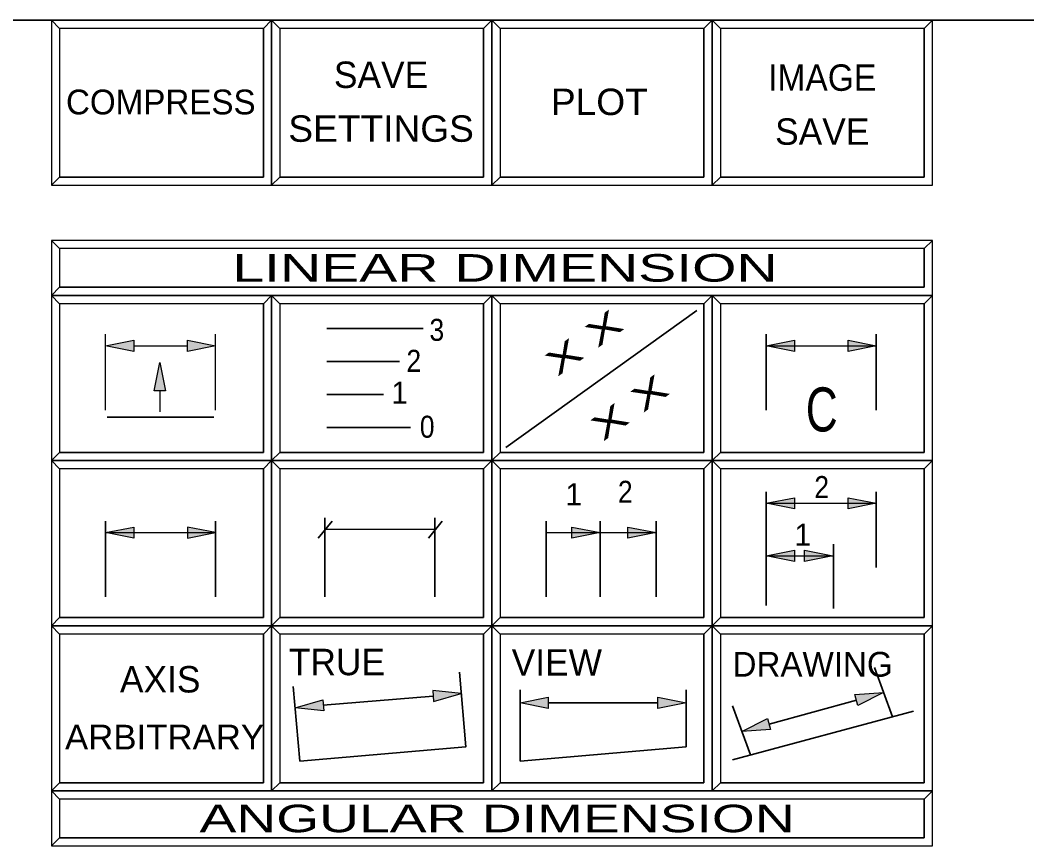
# Model space of a CAD drawing. Extents: x 95906.9 to 95918.9, y 90964.8 to 90972.9.
# Drawn here: x 95908.876 to 95910.704, y 90971.369 to 90972.862 of the extents above; entities that cross this region are included whole.
import ezdxf
from ezdxf.enums import TextEntityAlignment as Align

# ---------------------------------------------------------------- set-up
doc = ezdxf.new("R2010")
doc.units = 0
doc.header["$LTSCALE"] = 0.019
for name, color, linetype, lineweight in [('1', 7, 'Continuous', 25), ('11', 7, 'Continuous', 25), ('12', 7, 'Continuous', 25), ('17', 7, 'Continuous', 25), ('2', 7, 'Continuous', 13), ('3', 7, 'Continuous', 25), ('4', 7, 'Continuous', 35), ('6', 7, 'Continuous', 35), ('7', 7, 'Continuous', 35)]:
    doc.layers.add(name, color=color, linetype=linetype, lineweight=lineweight)

msp = doc.modelspace()

# ---------------------------------------------------------------- hatches: boundary and pattern name
at = {"layer": '6'}
for points in [[(95909.0307, 90972.2701), (95909.0819, 90972.2803), (95909.0819, 90972.2599)], [(95909.1793, 90972.2803), (95909.2305, 90972.2701), (95909.1793, 90972.2599)], [(95910.2307, 90972.2701), (95910.2819, 90972.2803), (95910.2819, 90972.2599)], [(95910.3793, 90972.2803), (95910.4305, 90972.2701), (95910.3793, 90972.2599)], [(95909.1291, 90972.2397), (95909.1393, 90972.1885), (95909.1189, 90972.1885)], [(95910.2307, 90971.9841), (95910.2819, 90971.9943), (95910.2819, 90971.9739)], [(95910.3793, 90971.9943), (95910.4305, 90971.9841), (95910.3793, 90971.9739)], [(95909.0307, 90971.9308), (95909.0819, 90971.941), (95909.0819, 90971.9206)], [(95909.2305, 90971.9308), (95909.1793, 90971.941), (95909.1793, 90971.9206)], [(95909.8778, 90971.941), (95909.929, 90971.9308), (95909.8778, 90971.9206)], [(95909.9793, 90971.941), (95910.0305, 90971.9308), (95909.9793, 90971.9206)], [(95910.2307, 90971.8889), (95910.2819, 90971.8991), (95910.2819, 90971.8787)], [(95910.3003, 90971.8991), (95910.3515, 90971.8889), (95910.3003, 90971.8787)], [(95909.6767, 90971.6384), (95909.6248, 90971.6443), (95909.6265, 90971.6239)], [(95910.3915, 90971.6366), (95910.4436, 90971.6403), (95910.397, 90971.6168)], [(95909.3751, 90971.6129), (95909.4253, 90971.6274), (95909.427, 90971.607)], [(95909.7835, 90971.6216), (95909.8347, 90971.6318), (95909.8347, 90971.6114)], [(95910.0339, 90971.6318), (95910.0851, 90971.6216), (95910.0339, 90971.6114)], [(95910.1865, 90971.5695), (95910.2331, 90971.593), (95910.2386, 90971.5732)]]:
    msp.add_hatch(color=256, dxfattribs=at).paths.add_polyline_path(points)

# ---------------------------------------------------------------- linework, layer by layer
at = {"layer": '1'}
for points in [[(95908.9323, 90972.5617), (95909.3323, 90972.5617), (95909.3323, 90972.8617), (95908.9323, 90972.8617)], [(95909.3323, 90972.5617), (95909.7323, 90972.5617), (95909.7323, 90972.8617), (95909.3323, 90972.8617)], [(95909.7323, 90972.5617), (95910.1323, 90972.5617), (95910.1323, 90972.8617), (95909.7323, 90972.8617)], [(95910.1323, 90972.5617), (95910.5323, 90972.5617), (95910.5323, 90972.8617), (95910.1323, 90972.8617)], [(95908.9323, 90972.3617), (95910.5323, 90972.3617), (95910.5323, 90972.4617), (95908.9323, 90972.4617)], [(95908.9323, 90972.0617), (95909.3323, 90972.0617), (95909.3323, 90972.3617), (95908.9323, 90972.3617)], [(95909.3323, 90972.0617), (95909.7323, 90972.0617), (95909.7323, 90972.3617), (95909.3323, 90972.3617)], [(95909.7323, 90972.0617), (95910.1323, 90972.0617), (95910.1323, 90972.3617), (95909.7323, 90972.3617)], [(95910.1323, 90972.0617), (95910.5323, 90972.0617), (95910.5323, 90972.3617), (95910.1323, 90972.3617)], [(95908.9323, 90971.7617), (95909.3323, 90971.7617), (95909.3323, 90972.0617), (95908.9323, 90972.0617)], [(95909.3323, 90971.7617), (95909.7323, 90971.7617), (95909.7323, 90972.0617), (95909.3323, 90972.0617)], [(95909.7323, 90971.7617), (95910.1323, 90971.7617), (95910.1323, 90972.0617), (95909.7323, 90972.0617)], [(95910.1323, 90971.7617), (95910.5323, 90971.7617), (95910.5323, 90972.0617), (95910.1323, 90972.0617)], [(95908.9323, 90971.4617), (95909.3323, 90971.4617), (95909.3323, 90971.7617), (95908.9323, 90971.7617)], [(95909.3323, 90971.4617), (95909.7323, 90971.4617), (95909.7323, 90971.7617), (95909.3323, 90971.7617)], [(95909.7323, 90971.4617), (95910.1323, 90971.4617), (95910.1323, 90971.7617), (95909.7323, 90971.7617)], [(95910.1323, 90971.4617), (95910.5323, 90971.4617), (95910.5323, 90971.7617), (95910.1323, 90971.7617)], [(95908.9323, 90971.3617), (95910.5323, 90971.3617), (95910.5323, 90971.4617), (95908.9323, 90971.4617)]]:
    msp.add_lwpolyline(points, close=True, dxfattribs=at)
at = {"layer": '11'}
for points in [[(95908.9473, 90972.5767), (95909.3173, 90972.5767), (95909.3173, 90972.8467), (95908.9473, 90972.8467)], [(95909.3473, 90972.5767), (95909.7173, 90972.5767), (95909.7173, 90972.8467), (95909.3473, 90972.8467)], [(95909.7473, 90972.5767), (95910.1173, 90972.5767), (95910.1173, 90972.8467), (95909.7473, 90972.8467)], [(95910.1473, 90972.5767), (95910.5173, 90972.5767), (95910.5173, 90972.8467), (95910.1473, 90972.8467)], [(95908.9473, 90972.0767), (95909.3173, 90972.0767), (95909.3173, 90972.3467), (95908.9473, 90972.3467)], [(95909.3473, 90972.0767), (95909.7173, 90972.0767), (95909.7173, 90972.3467), (95909.3473, 90972.3467)], [(95909.7473, 90972.0767), (95910.1173, 90972.0767), (95910.1173, 90972.3467), (95909.7473, 90972.3467)], [(95910.1473, 90972.0767), (95910.5173, 90972.0767), (95910.5173, 90972.3467), (95910.1473, 90972.3467)], [(95908.9473, 90971.7767), (95909.3173, 90971.7767), (95909.3173, 90972.0467), (95908.9473, 90972.0467)], [(95909.3473, 90971.7767), (95909.7173, 90971.7767), (95909.7173, 90972.0467), (95909.3473, 90972.0467)], [(95909.7473, 90971.7767), (95910.1173, 90971.7767), (95910.1173, 90972.0467), (95909.7473, 90972.0467)], [(95910.1473, 90971.7767), (95910.5173, 90971.7767), (95910.5173, 90972.0467), (95910.1473, 90972.0467)], [(95908.9473, 90971.4767), (95909.3173, 90971.4767), (95909.3173, 90971.7467), (95908.9473, 90971.7467)], [(95909.3473, 90971.4767), (95909.7173, 90971.4767), (95909.7173, 90971.7467), (95909.3473, 90971.7467)], [(95909.7473, 90971.4767), (95910.1173, 90971.4767), (95910.1173, 90971.7467), (95909.7473, 90971.7467)], [(95910.1473, 90971.4767), (95910.5173, 90971.4767), (95910.5173, 90971.7467), (95910.1473, 90971.7467)]]:
    msp.add_lwpolyline(points, close=True, dxfattribs=at)
at = {"layer": '12'}
for points in [[(95910.1473, 90972.5767), (95910.5173, 90972.5767), (95910.5173, 90972.8467), (95910.1473, 90972.8467)], [(95908.9473, 90971.7767), (95909.3173, 90971.7767), (95909.3173, 90972.0467), (95908.9473, 90972.0467)]]:
    msp.add_lwpolyline(points, close=True, dxfattribs=at)
at = {"layer": '17'}
for points in [[(95908.9473, 90972.3767), (95910.5173, 90972.3767), (95910.5173, 90972.4467), (95908.9473, 90972.4467)], [(95908.9473, 90971.3767), (95910.5173, 90971.3767), (95910.5173, 90971.4467), (95908.9473, 90971.4467)]]:
    msp.add_lwpolyline(points, close=True, dxfattribs=at)
at = {"layer": '2'}
for points in [[(95908.9323, 90972.8617), (95908.9323, 90972.5617), (95908.9473, 90972.5767), (95908.9473, 90972.8467), (95909.3173, 90972.8467), (95909.3323, 90972.8617)], [(95909.3323, 90972.8617), (95909.3323, 90972.5617), (95909.3473, 90972.5767), (95909.3473, 90972.8467), (95909.7173, 90972.8467), (95909.7323, 90972.8617)], [(95909.7323, 90972.8617), (95909.7323, 90972.5617), (95909.7473, 90972.5767), (95909.7473, 90972.8467), (95910.1173, 90972.8467), (95910.1323, 90972.8617)], [(95910.1323, 90972.8617), (95910.1323, 90972.5617), (95910.1473, 90972.5767), (95910.1473, 90972.8467), (95910.5173, 90972.8467), (95910.5323, 90972.8617)], [(95908.9323, 90972.4617), (95908.9323, 90972.3617), (95908.9473, 90972.3767), (95908.9473, 90972.4467), (95910.5173, 90972.4467), (95910.5323, 90972.4617)], [(95908.9323, 90972.3617), (95908.9323, 90972.0617), (95908.9473, 90972.0767), (95908.9473, 90972.3467), (95909.3173, 90972.3467), (95909.3323, 90972.3617)], [(95909.3323, 90972.3617), (95909.3323, 90972.0617), (95909.3473, 90972.0767), (95909.3473, 90972.3467), (95909.7173, 90972.3467), (95909.7323, 90972.3617)], [(95909.7323, 90972.3617), (95909.7323, 90972.0617), (95909.7473, 90972.0767), (95909.7473, 90972.3467), (95910.1173, 90972.3467), (95910.1323, 90972.3617)], [(95910.1323, 90972.3617), (95910.1323, 90972.0617), (95910.1473, 90972.0767), (95910.1473, 90972.3467), (95910.5173, 90972.3467), (95910.5323, 90972.3617)], [(95908.9323, 90972.0617), (95908.9323, 90971.7617), (95908.9473, 90971.7767), (95908.9473, 90972.0467), (95909.3173, 90972.0467), (95909.3323, 90972.0617)], [(95909.3323, 90972.0617), (95909.3323, 90971.7617), (95909.3473, 90971.7767), (95909.3473, 90972.0467), (95909.7173, 90972.0467), (95909.7323, 90972.0617)], [(95909.7323, 90972.0617), (95909.7323, 90971.7617), (95909.7473, 90971.7767), (95909.7473, 90972.0467), (95910.1173, 90972.0467), (95910.1323, 90972.0617)], [(95910.1323, 90972.0617), (95910.1323, 90971.7617), (95910.1473, 90971.7767), (95910.1473, 90972.0467), (95910.5173, 90972.0467), (95910.5323, 90972.0617)], [(95908.9323, 90971.7617), (95908.9323, 90971.4617), (95908.9473, 90971.4767), (95908.9473, 90971.7467), (95909.3173, 90971.7467), (95909.3323, 90971.7617)], [(95909.3323, 90971.7617), (95909.3323, 90971.4617), (95909.3473, 90971.4767), (95909.3473, 90971.7467), (95909.7173, 90971.7467), (95909.7323, 90971.7617)], [(95909.7323, 90971.7617), (95909.7323, 90971.4617), (95909.7473, 90971.4767), (95909.7473, 90971.7467), (95910.1173, 90971.7467), (95910.1323, 90971.7617)], [(95910.1323, 90971.7617), (95910.1323, 90971.4617), (95910.1473, 90971.4767), (95910.1473, 90971.7467), (95910.5173, 90971.7467), (95910.5323, 90971.7617)], [(95908.9323, 90971.4617), (95908.9323, 90971.3617), (95908.9473, 90971.3767), (95908.9473, 90971.4467), (95910.5173, 90971.4467), (95910.5323, 90971.4617)]]:
    msp.add_lwpolyline(points, close=True, dxfattribs=at)
at = {"layer": '3'}
for points in [[(95908.9323, 90972.5617), (95909.3323, 90972.5617), (95909.3323, 90972.8617), (95909.3173, 90972.8467), (95909.3173, 90972.5767), (95908.9473, 90972.5767)], [(95909.3323, 90972.5617), (95909.7323, 90972.5617), (95909.7323, 90972.8617), (95909.7173, 90972.8467), (95909.7173, 90972.5767), (95909.3473, 90972.5767)], [(95909.7323, 90972.5617), (95910.1323, 90972.5617), (95910.1323, 90972.8617), (95910.1173, 90972.8467), (95910.1173, 90972.5767), (95909.7473, 90972.5767)], [(95910.1323, 90972.5617), (95910.5323, 90972.5617), (95910.5323, 90972.8617), (95910.5173, 90972.8467), (95910.5173, 90972.5767), (95910.1473, 90972.5767)], [(95908.9323, 90972.3617), (95910.5323, 90972.3617), (95910.5323, 90972.4617), (95910.5173, 90972.4467), (95910.5173, 90972.3767), (95908.9473, 90972.3767)], [(95908.9323, 90972.0617), (95909.3323, 90972.0617), (95909.3323, 90972.3617), (95909.3173, 90972.3467), (95909.3173, 90972.0767), (95908.9473, 90972.0767)], [(95909.3323, 90972.0617), (95909.7323, 90972.0617), (95909.7323, 90972.3617), (95909.7173, 90972.3467), (95909.7173, 90972.0767), (95909.3473, 90972.0767)], [(95909.7323, 90972.0617), (95910.1323, 90972.0617), (95910.1323, 90972.3617), (95910.1173, 90972.3467), (95910.1173, 90972.0767), (95909.7473, 90972.0767)], [(95910.1323, 90972.0617), (95910.5323, 90972.0617), (95910.5323, 90972.3617), (95910.5173, 90972.3467), (95910.5173, 90972.0767), (95910.1473, 90972.0767)], [(95908.9323, 90971.7617), (95909.3323, 90971.7617), (95909.3323, 90972.0617), (95909.3173, 90972.0467), (95909.3173, 90971.7767), (95908.9473, 90971.7767)], [(95909.3323, 90971.7617), (95909.7323, 90971.7617), (95909.7323, 90972.0617), (95909.7173, 90972.0467), (95909.7173, 90971.7767), (95909.3473, 90971.7767)], [(95909.7323, 90971.7617), (95910.1323, 90971.7617), (95910.1323, 90972.0617), (95910.1173, 90972.0467), (95910.1173, 90971.7767), (95909.7473, 90971.7767)], [(95910.1323, 90971.7617), (95910.5323, 90971.7617), (95910.5323, 90972.0617), (95910.5173, 90972.0467), (95910.5173, 90971.7767), (95910.1473, 90971.7767)], [(95908.9323, 90971.4617), (95909.3323, 90971.4617), (95909.3323, 90971.7617), (95909.3173, 90971.7467), (95909.3173, 90971.4767), (95908.9473, 90971.4767)], [(95909.3323, 90971.4617), (95909.7323, 90971.4617), (95909.7323, 90971.7617), (95909.7173, 90971.7467), (95909.7173, 90971.4767), (95909.3473, 90971.4767)], [(95909.7323, 90971.4617), (95910.1323, 90971.4617), (95910.1323, 90971.7617), (95910.1173, 90971.7467), (95910.1173, 90971.4767), (95909.7473, 90971.4767)], [(95910.1323, 90971.4617), (95910.5323, 90971.4617), (95910.5323, 90971.7617), (95910.5173, 90971.7467), (95910.5173, 90971.4767), (95910.1473, 90971.4767)], [(95908.9323, 90971.3617), (95910.5323, 90971.3617), (95910.5323, 90971.4617), (95910.5173, 90971.4467), (95910.5173, 90971.3767), (95908.9473, 90971.3767)]]:
    msp.add_lwpolyline(points, close=True, dxfattribs=at)
at = {"layer": '4'}
for p, q in [((95908.9473, 90972.8467), (95908.9323, 90972.8617)), ((95909.3473, 90972.8467), (95909.3323, 90972.8617)), ((95909.7473, 90972.8467), (95909.7323, 90972.8617)), ((95910.1473, 90972.8467), (95910.1323, 90972.8617)), ((95908.9473, 90972.4467), (95908.9323, 90972.4617)), ((95908.9473, 90972.3467), (95908.9323, 90972.3617)), ((95908.9473, 90972.3467), (95908.9323, 90972.3617)), ((95909.3473, 90972.3467), (95909.3323, 90972.3617)), ((95909.7473, 90972.3467), (95909.7323, 90972.3617)), ((95910.1473, 90972.3467), (95910.1323, 90972.3617)), ((95908.9473, 90972.0467), (95908.9323, 90972.0617)), ((95909.3473, 90972.0467), (95909.3323, 90972.0617)), ((95909.7473, 90972.0467), (95909.7323, 90972.0617)), ((95910.1473, 90972.0467), (95910.1323, 90972.0617)), ((95908.9473, 90971.7467), (95908.9323, 90971.7617)), ((95909.3473, 90971.7467), (95909.3323, 90971.7617)), ((95909.7473, 90971.7467), (95909.7323, 90971.7617)), ((95910.1473, 90971.7467), (95910.1323, 90971.7617)), ((95908.9473, 90971.4467), (95908.9323, 90971.4617))]:
    msp.add_line(p, q, dxfattribs=at)
at = {"layer": '6'}
for p, q in [((95909.7575, 90972.0856), (95910.1045, 90972.3341)), ((95909.4323, 90972.3017), (95909.6076, 90972.3017)), ((95910.2307, 90972.1533), (95910.2307, 90972.2912)), ((95910.4305, 90972.1533), (95910.4305, 90972.2912)), ((95909.4323, 90972.2417), (95909.5646, 90972.2417)), ((95909.4323, 90972.1817), (95909.5356, 90972.1817)), ((95909.0334, 90972.1407), (95909.2276, 90972.1407)), ((95909.4323, 90972.1217), (95909.5847, 90972.1217)), ((95910.2307, 90971.7987), (95910.2307, 90972.0052)), ((95910.4305, 90971.8673), (95910.4305, 90972.0052)), ((95909.0307, 90971.814), (95909.0307, 90971.9519)), ((95909.2305, 90971.814), (95909.2305, 90971.9519)), ((95909.417, 90971.921), (95909.4423, 90971.9518)), ((95909.4289, 90971.814), (95909.4289, 90971.958)), ((95909.6169, 90971.921), (95909.6422, 90971.9518)), ((95909.6287, 90971.814), (95909.6287, 90971.958)), ((95909.8307, 90971.814), (95909.8307, 90971.9519)), ((95909.929, 90971.814), (95909.929, 90971.9519)), ((95910.0305, 90971.814), (95910.0305, 90971.9519)), ((95910.3526, 90971.7929), (95910.3526, 90971.91)), ((95910.4596, 90971.5961), (95910.427, 90971.6856)), ((95909.3835, 90971.5155), (95909.3716, 90971.6512)), ((95909.7835, 90971.5155), (95909.7835, 90971.6454)), ((95909.4261, 90971.6172), (95909.6256, 90971.6341)), ((95909.8347, 90971.6216), (95910.0339, 90971.6216)), ((95910.2358, 90971.5831), (95910.3943, 90971.6267)), ((95910.2019, 90971.527), (95910.1693, 90971.6165)), ((95910.1695, 90971.5183), (95910.4981, 90971.6064))]:
    msp.add_line(p, q, dxfattribs=at)
at = {"layer": '6', "lineweight": 25}
for p, q in [((95909.0307, 90972.1533), (95909.0307, 90972.2912)), ((95909.2305, 90972.1533), (95909.2305, 90972.2912)), ((95909.0819, 90972.2701), (95909.1793, 90972.2701)), ((95910.2307, 90972.2701), (95910.4305, 90972.2701)), ((95909.1291, 90972.1885), (95909.1291, 90972.1503)), ((95910.2307, 90971.9841), (95910.4305, 90971.9841)), ((95909.4289, 90971.9369), (95909.6287, 90971.9369)), ((95909.0307, 90971.9308), (95909.2305, 90971.9308)), ((95909.8307, 90971.9308), (95910.0305, 90971.9308)), ((95910.2307, 90971.8889), (95910.3515, 90971.8889))]:
    msp.add_line(p, q, dxfattribs=at)
for points in [[(95909.0307, 90972.2701), (95909.0819, 90972.2803), (95909.0819, 90972.2599)], [(95909.1793, 90972.2803), (95909.2305, 90972.2701), (95909.1793, 90972.2599)], [(95910.2307, 90972.2701), (95910.2819, 90972.2803), (95910.2819, 90972.2599)], [(95910.3793, 90972.2803), (95910.4305, 90972.2701), (95910.3793, 90972.2599)], [(95909.1291, 90972.2397), (95909.1393, 90972.1885), (95909.1189, 90972.1885)], [(95910.2307, 90971.9841), (95910.2819, 90971.9943), (95910.2819, 90971.9739)], [(95910.3793, 90971.9943), (95910.4305, 90971.9841), (95910.3793, 90971.9739)], [(95909.0307, 90971.9308), (95909.0819, 90971.941), (95909.0819, 90971.9206)], [(95909.2305, 90971.9308), (95909.1793, 90971.941), (95909.1793, 90971.9206)], [(95909.8778, 90971.941), (95909.929, 90971.9308), (95909.8778, 90971.9206)], [(95909.9793, 90971.941), (95910.0305, 90971.9308), (95909.9793, 90971.9206)], [(95910.2307, 90971.8889), (95910.2819, 90971.8991), (95910.2819, 90971.8787)], [(95910.3003, 90971.8991), (95910.3515, 90971.8889), (95910.3003, 90971.8787)], [(95909.6767, 90971.6384), (95909.6248, 90971.6443), (95909.6265, 90971.6239)], [(95910.3915, 90971.6366), (95910.4436, 90971.6403), (95910.397, 90971.6168)], [(95909.3751, 90971.6129), (95909.4253, 90971.6274), (95909.427, 90971.607)], [(95909.7835, 90971.6216), (95909.8347, 90971.6318), (95909.8347, 90971.6114)], [(95910.0339, 90971.6318), (95910.0851, 90971.6216), (95910.0339, 90971.6114)], [(95910.1865, 90971.5695), (95910.2331, 90971.593), (95910.2386, 90971.5732)]]:
    msp.add_lwpolyline(points, close=True, dxfattribs=at)
at = {"layer": '6'}
for points in [[(95909.3835, 90971.5155), (95909.6851, 90971.5419), (95909.6732, 90971.6776)], [(95909.7835, 90971.5155), (95910.0851, 90971.5419), (95910.0851, 90971.6454)]]:
    msp.add_lwpolyline(points, dxfattribs=at)
at = {"layer": '7'}
msp.add_lwpolyline([(95906.8548, 90972.8617), (95918.8548, 90972.8617), (95918.8548, 90964.7617), (95906.8548, 90964.7617)], close=True, dxfattribs=at)

# ---------------------------------------------------------------- texts
at = {"layer": '6'}
for s, height, p in [('SAVE', 0.048, (95909.531, 90972.7385)), ('COMPRESS', 0.045, (95909.131, 90972.6905)), ('SAVE', 0.048, (95910.3323, 90972.6353)), ('1', 0.04, (95909.5646, 90972.1652)), ('1', 0.04, (95909.881, 90971.9806)), ('1', 0.04, (95910.2969, 90971.9071)), ('TRUE', 0.048, (95909.4509, 90971.6719)), ('VIEW', 0.048, (95909.8503, 90971.6711)), ('DRAWING', 0.045, (95910.3148, 90971.6692)), ('AXIS', 0.048, (95909.1299, 90971.6405))]:
    msp.add_text(s, height=height, dxfattribs=at).set_placement(p, align=Align.CENTER)
for s, height, width, p in [('IMAGE', 0.048, 0.95, (95910.3322, 90972.7333)), ('PLOT', 0.048, 1.05, (95909.9275, 90972.6893)), ('SETTINGS', 0.048, 1.05, (95909.5311, 90972.6407)), ('3', 0.04, 0.9, (95909.6323, 90972.2792)), ('2', 0.04, 0.9, (95909.5905, 90972.2229)), ('0', 0.04, 0.9, (95909.6148, 90972.1032)), ('2', 0.04, 0.9, (95909.9746, 90971.985)), ('2', 0.04, 0.9, (95910.3313, 90971.9936)), ('ARBITRARY', 0.045, 1.05, (95909.1378, 90971.537))]:
    msp.add_text(s, height=height, dxfattribs=dict(at, width=width)).set_placement(p, align=Align.CENTER)
at = {"layer": '6', "width": 1.55}
for p in [(95909.949, 90972.2836), (95909.8764, 90972.2316), (95910.0318, 90972.1659), (95909.9592, 90972.1139)]:
    msp.add_text('X', height=0.045, rotation=35.608, dxfattribs=at).set_placement(p, align=Align.CENTER)
at = {"layer": '6', "width": 0.75}
msp.add_text('C', height=0.08, dxfattribs=at).set_placement((95910.3024, 90972.1146))
at = {"layer": '7'}
for s, width, p in [('    LINEAR DIMENSION   ', 1.55, (95909.7418, 90972.3867)), ('   ANGULAR DIMENSION   ', 1.5, (95909.7418, 90971.3867))]:
    msp.add_text(s, height=0.04999, dxfattribs=dict(at, width=width)).set_placement(p, align=Align.CENTER)

doc.saveas('drawing.dxf')
